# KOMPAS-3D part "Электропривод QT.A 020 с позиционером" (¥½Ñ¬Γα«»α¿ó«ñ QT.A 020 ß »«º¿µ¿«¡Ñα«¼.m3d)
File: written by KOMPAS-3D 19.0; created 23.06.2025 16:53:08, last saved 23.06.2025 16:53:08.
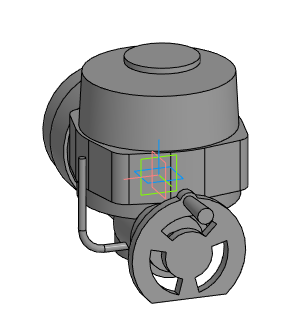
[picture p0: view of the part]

Document properties: Автор: Евгений; Полное имя файла: E:\Dendor Работа Сачек\3D для проектировщиков\3.5 Тип QT.А Электропривод\stp_Электропривод QT.A с позиционером\Электропривод QT.A 020 с позиционером.m3d

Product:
- Part/product: Электропривод QT.A 020 с позиционером

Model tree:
1. Операция без истории:1  (labels: Электропривод QT.A 020 с позиционером)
